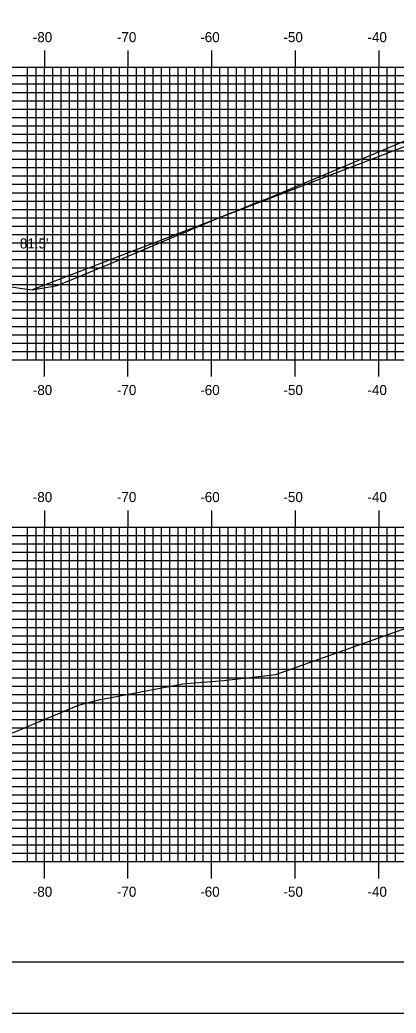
# Model space of a CAD drawing. Extents: x 852147 to 852490, y 364661 to 364881.
# Drawn here: x 852229.8 to 852274.8, y 364661.3 to 364780 of the extents above; entities that cross this region are included whole.
import ezdxf

# ---------------------------------------------------------------- set-up
doc = ezdxf.new("R2010")
doc.units = 0
for name, color, linetype in [('BORDER', 7, 'Continuous'), ('D_Roadway_SlopeLines', 7, 'Continuous'), ('D_Text_Standard', 7, 'Continuous'), ('H_V ANNOTATION', 7, 'Continuous'), ('MAJOR', 7, 'Continuous'), ('MINOR', 7, 'Continuous'), ('PLOT BOUNDARY', 7, 'Continuous'), ('S_Roadway_Centerline', 7, 'Continuous')]:
    doc.layers.add(name, color=color, linetype=linetype)

msp = doc.modelspace()

# ---------------------------------------------------------------- linework, layer by layer
at = {"layer": 'BORDER'}
msp.add_lwpolyline([(852163.16, 364667.37), (852483.16, 364667.37), (852483.16, 364877.37), (852163.16, 364877.37)], close=True, dxfattribs=at)
at = {"layer": 'D_Roadway_SlopeLines'}
msp.add_line((852285.76, 364768.68), (852231.3, 364747.76), dxfattribs=at)
at = {"layer": 'MAJOR'}
for p, q in [((852232.76, 364776.37), (852232.76, 364774.37)), ((852242.76, 364776.37), (852242.76, 364774.37)), ((852252.76, 364776.37), (852252.76, 364774.37)), ((852262.76, 364776.37), (852262.76, 364774.37)), ((852272.76, 364776.37), (852272.76, 364774.37)), ((852172.76, 364774.37), (852452.76, 364774.37)), ((852172.76, 364774.37), (852452.76, 364774.37)), ((852232.76, 364739.37), (852232.76, 364774.37)), ((852242.76, 364739.37), (852242.76, 364774.37)), ((852252.76, 364739.37), (852252.76, 364774.37)), ((852262.76, 364739.37), (852262.76, 364774.37)), ((852272.76, 364739.37), (852272.76, 364774.37)), ((852172.76, 364769.37), (852452.76, 364769.37)), ((852172.76, 364764.37), (852452.76, 364764.37)), ((852172.76, 364759.37), (852452.76, 364759.37)), ((852172.76, 364754.37), (852452.76, 364754.37)), ((852172.76, 364749.37), (852452.76, 364749.37)), ((852172.76, 364744.37), (852452.76, 364744.37)), ((852172.76, 364739.37), (852452.76, 364739.37)), ((852172.76, 364739.37), (852452.76, 364739.37)), ((852232.76, 364737.37), (852232.76, 364739.37)), ((852242.76, 364737.37), (852242.76, 364739.37)), ((852252.76, 364737.37), (852252.76, 364739.37)), ((852262.76, 364737.37), (852262.76, 364739.37)), ((852272.76, 364737.37), (852272.76, 364739.37)), ((852232.76, 364721.37), (852232.76, 364719.37)), ((852242.76, 364721.37), (852242.76, 364719.37)), ((852252.76, 364721.37), (852252.76, 364719.37)), ((852262.76, 364721.37), (852262.76, 364719.37)), ((852272.76, 364721.37), (852272.76, 364719.37)), ((852172.76, 364719.37), (852452.76, 364719.37)), ((852172.76, 364719.37), (852452.76, 364719.37)), ((852232.76, 364679.37), (852232.76, 364719.37)), ((852242.76, 364679.37), (852242.76, 364719.37)), ((852252.76, 364679.37), (852252.76, 364719.37)), ((852262.76, 364679.37), (852262.76, 364719.37)), ((852272.76, 364679.37), (852272.76, 364719.37)), ((852172.76, 364714.37), (852452.76, 364714.37)), ((852172.76, 364709.37), (852452.76, 364709.37)), ((852172.76, 364704.37), (852452.76, 364704.37)), ((852172.76, 364699.37), (852452.76, 364699.37)), ((852172.76, 364694.37), (852452.76, 364694.37)), ((852172.76, 364689.37), (852452.76, 364689.37)), ((852172.76, 364684.37), (852452.76, 364684.37)), ((852172.76, 364679.37), (852452.76, 364679.37)), ((852172.76, 364679.37), (852452.76, 364679.37)), ((852232.76, 364677.37), (852232.76, 364679.37)), ((852242.76, 364677.37), (852242.76, 364679.37)), ((852252.76, 364677.37), (852252.76, 364679.37)), ((852262.76, 364677.37), (852262.76, 364679.37)), ((852272.76, 364677.37), (852272.76, 364679.37))]:
    msp.add_line(p, q, dxfattribs=at)
at = {"layer": 'MINOR'}
for p, q in [((852230.76, 364739.37), (852230.76, 364774.37)), ((852231.76, 364739.37), (852231.76, 364774.37)), ((852233.76, 364739.37), (852233.76, 364774.37)), ((852234.76, 364739.37), (852234.76, 364774.37)), ((852235.76, 364739.37), (852235.76, 364774.37)), ((852236.76, 364739.37), (852236.76, 364774.37)), ((852237.76, 364739.37), (852237.76, 364774.37)), ((852238.76, 364739.37), (852238.76, 364774.37)), ((852239.76, 364739.37), (852239.76, 364774.37)), ((852240.76, 364739.37), (852240.76, 364774.37)), ((852241.76, 364739.37), (852241.76, 364774.37)), ((852243.76, 364739.37), (852243.76, 364774.37)), ((852244.76, 364739.37), (852244.76, 364774.37)), ((852245.76, 364739.37), (852245.76, 364774.37)), ((852246.76, 364739.37), (852246.76, 364774.37)), ((852247.76, 364739.37), (852247.76, 364774.37)), ((852248.76, 364739.37), (852248.76, 364774.37)), ((852249.76, 364739.37), (852249.76, 364774.37)), ((852250.76, 364739.37), (852250.76, 364774.37)), ((852251.76, 364739.37), (852251.76, 364774.37)), ((852253.76, 364739.37), (852253.76, 364774.37)), ((852254.76, 364739.37), (852254.76, 364774.37)), ((852255.76, 364739.37), (852255.76, 364774.37)), ((852256.76, 364739.37), (852256.76, 364774.37)), ((852257.76, 364739.37), (852257.76, 364774.37)), ((852258.76, 364739.37), (852258.76, 364774.37)), ((852259.76, 364739.37), (852259.76, 364774.37)), ((852260.76, 364739.37), (852260.76, 364774.37)), ((852261.76, 364739.37), (852261.76, 364774.37)), ((852263.76, 364739.37), (852263.76, 364774.37)), ((852264.76, 364739.37), (852264.76, 364774.37)), ((852265.76, 364739.37), (852265.76, 364774.37)), ((852266.76, 364739.37), (852266.76, 364774.37)), ((852267.76, 364739.37), (852267.76, 364774.37)), ((852268.76, 364739.37), (852268.76, 364774.37)), ((852269.76, 364739.37), (852269.76, 364774.37)), ((852270.76, 364739.37), (852270.76, 364774.37)), ((852271.76, 364739.37), (852271.76, 364774.37)), ((852273.76, 364739.37), (852273.76, 364774.37)), ((852274.76, 364739.37), (852274.76, 364774.37)), ((852172.76, 364773.37), (852452.76, 364773.37)), ((852172.76, 364772.37), (852452.76, 364772.37)), ((852172.76, 364771.37), (852452.76, 364771.37)), ((852172.76, 364770.37), (852452.76, 364770.37)), ((852172.76, 364768.37), (852452.76, 364768.37)), ((852172.76, 364767.37), (852452.76, 364767.37)), ((852172.76, 364766.37), (852452.76, 364766.37)), ((852172.76, 364765.37), (852452.76, 364765.37)), ((852172.76, 364763.37), (852452.76, 364763.37)), ((852172.76, 364762.37), (852452.76, 364762.37)), ((852172.76, 364761.37), (852452.76, 364761.37)), ((852172.76, 364760.37), (852452.76, 364760.37)), ((852172.76, 364758.37), (852452.76, 364758.37)), ((852172.76, 364757.37), (852452.76, 364757.37)), ((852172.76, 364756.37), (852452.76, 364756.37)), ((852172.76, 364755.37), (852452.76, 364755.37)), ((852172.76, 364753.37), (852452.76, 364753.37)), ((852172.76, 364752.37), (852452.76, 364752.37)), ((852172.76, 364751.37), (852452.76, 364751.37)), ((852172.76, 364750.37), (852452.76, 364750.37)), ((852172.76, 364748.37), (852452.76, 364748.37)), ((852172.76, 364747.37), (852452.76, 364747.37)), ((852172.76, 364746.37), (852452.76, 364746.37)), ((852172.76, 364745.37), (852452.76, 364745.37)), ((852172.76, 364743.37), (852452.76, 364743.37)), ((852172.76, 364742.37), (852452.76, 364742.37)), ((852172.76, 364741.37), (852452.76, 364741.37)), ((852172.76, 364740.37), (852452.76, 364740.37)), ((852172.76, 364718.37), (852452.76, 364718.37)), ((852230.76, 364679.37), (852230.76, 364719.37)), ((852231.76, 364679.37), (852231.76, 364719.37)), ((852233.76, 364679.37), (852233.76, 364719.37)), ((852234.76, 364679.37), (852234.76, 364719.37)), ((852235.76, 364679.37), (852235.76, 364719.37)), ((852236.76, 364679.37), (852236.76, 364719.37)), ((852237.76, 364679.37), (852237.76, 364719.37)), ((852238.76, 364679.37), (852238.76, 364719.37)), ((852239.76, 364679.37), (852239.76, 364719.37)), ((852240.76, 364679.37), (852240.76, 364719.37)), ((852241.76, 364679.37), (852241.76, 364719.37)), ((852243.76, 364679.37), (852243.76, 364719.37)), ((852244.76, 364679.37), (852244.76, 364719.37)), ((852245.76, 364679.37), (852245.76, 364719.37)), ((852246.76, 364679.37), (852246.76, 364719.37)), ((852247.76, 364679.37), (852247.76, 364719.37)), ((852248.76, 364679.37), (852248.76, 364719.37)), ((852249.76, 364679.37), (852249.76, 364719.37)), ((852250.76, 364679.37), (852250.76, 364719.37)), ((852251.76, 364679.37), (852251.76, 364719.37)), ((852253.76, 364679.37), (852253.76, 364719.37)), ((852254.76, 364679.37), (852254.76, 364719.37)), ((852255.76, 364679.37), (852255.76, 364719.37)), ((852256.76, 364679.37), (852256.76, 364719.37)), ((852257.76, 364679.37), (852257.76, 364719.37)), ((852258.76, 364679.37), (852258.76, 364719.37)), ((852259.76, 364679.37), (852259.76, 364719.37)), ((852260.76, 364679.37), (852260.76, 364719.37)), ((852261.76, 364679.37), (852261.76, 364719.37)), ((852263.76, 364679.37), (852263.76, 364719.37)), ((852264.76, 364679.37), (852264.76, 364719.37)), ((852265.76, 364679.37), (852265.76, 364719.37)), ((852266.76, 364679.37), (852266.76, 364719.37)), ((852267.76, 364679.37), (852267.76, 364719.37)), ((852268.76, 364679.37), (852268.76, 364719.37)), ((852269.76, 364679.37), (852269.76, 364719.37)), ((852270.76, 364679.37), (852270.76, 364719.37)), ((852271.76, 364679.37), (852271.76, 364719.37)), ((852273.76, 364679.37), (852273.76, 364719.37)), ((852274.76, 364679.37), (852274.76, 364719.37)), ((852172.76, 364717.37), (852452.76, 364717.37)), ((852172.76, 364716.37), (852452.76, 364716.37)), ((852172.76, 364715.37), (852452.76, 364715.37)), ((852172.76, 364713.37), (852452.76, 364713.37)), ((852172.76, 364712.37), (852452.76, 364712.37)), ((852172.76, 364711.37), (852452.76, 364711.37)), ((852172.76, 364710.37), (852452.76, 364710.37)), ((852172.76, 364708.37), (852452.76, 364708.37)), ((852172.76, 364707.37), (852452.76, 364707.37)), ((852172.76, 364706.37), (852452.76, 364706.37)), ((852172.76, 364705.37), (852452.76, 364705.37)), ((852172.76, 364703.37), (852452.76, 364703.37)), ((852172.76, 364702.37), (852452.76, 364702.37)), ((852172.76, 364701.37), (852452.76, 364701.37)), ((852172.76, 364700.37), (852452.76, 364700.37)), ((852172.76, 364698.37), (852452.76, 364698.37)), ((852172.76, 364697.37), (852452.76, 364697.37)), ((852172.76, 364696.37), (852452.76, 364696.37)), ((852172.76, 364695.37), (852452.76, 364695.37)), ((852172.76, 364693.37), (852452.76, 364693.37)), ((852172.76, 364692.37), (852452.76, 364692.37)), ((852172.76, 364691.37), (852452.76, 364691.37)), ((852172.76, 364690.37), (852452.76, 364690.37)), ((852172.76, 364688.37), (852452.76, 364688.37)), ((852172.76, 364687.37), (852452.76, 364687.37)), ((852172.76, 364686.37), (852452.76, 364686.37)), ((852172.76, 364685.37), (852452.76, 364685.37)), ((852172.76, 364683.37), (852452.76, 364683.37)), ((852172.76, 364682.37), (852452.76, 364682.37)), ((852172.76, 364681.37), (852452.76, 364681.37)), ((852172.76, 364680.37), (852452.76, 364680.37))]:
    msp.add_line(p, q, dxfattribs=at)
at = {"layer": 'PLOT BOUNDARY'}
msp.add_lwpolyline([(852146.97, 364661.25), (852486.97, 364661.25), (852486.97, 364881.25), (852146.97, 364881.25)], close=True, dxfattribs=at)
at = {"layer": 'S_Roadway_Centerline'}
for points in [[(852224.08, 364748.8), (852230.42, 364747.89), (852231.3, 364747.76), (852233.36, 364748.09), (852234.28, 364748.26), (852235.28, 364748.65), (852241.08, 364751.04), (852254.88, 364756.88), (852255.35, 364757.03), (852256.42, 364757.46), (852257.84, 364758.08), (852259.46, 364758.66), (852280.54, 364767.54)], [(852228.88, 364694.73), (852235.14, 364697.36), (852236.84, 364698.07), (852239.27, 364698.72), (852249.31, 364700.62), (852254.2, 364701.02), (852260.43, 364701.74), (852280.28, 364708.79), (852284.03, 364710.04), (852284.87, 364710.01), (852295.09, 364709.66), (852297.1, 364709.56), (852299.39, 364709.49), (852305.93, 364709.05), (852313.49, 364708.62), (852316.43, 364708.48), (852318.4, 364708.34), (852330.85, 364706.15), (852335.84, 364705.07), (852344.14, 364703.12), (852356.99, 364700.16), (852360.48, 364700.01), (852373.76, 364699.54)]]:
    msp.add_lwpolyline(points, dxfattribs=at)

# ---------------------------------------------------------------- texts
at = {"layer": 'D_Text_Standard'}
msp.add_text("81.5'", height=1.2, dxfattribs=at).set_placement((852229.83, 364752.7))
at = {"layer": 'H_V ANNOTATION'}
for s, p in [('-80', (852231.38, 364777.37)), ('-70', (852241.44, 364777.37)), ('-60', (852251.41, 364777.37)), ('-50', (852261.36, 364777.37)), ('-40', (852271.41, 364777.37)), ('-80', (852231.38, 364735.17)), ('-70', (852241.44, 364735.17)), ('-60', (852251.41, 364735.17)), ('-50', (852261.36, 364735.17)), ('-40', (852271.41, 364735.17)), ('-80', (852231.38, 364722.37)), ('-70', (852241.44, 364722.37)), ('-60', (852251.41, 364722.37)), ('-50', (852261.36, 364722.37)), ('-40', (852271.41, 364722.37)), ('-80', (852231.38, 364675.17)), ('-70', (852241.44, 364675.17)), ('-60', (852251.41, 364675.17)), ('-50', (852261.36, 364675.17)), ('-40', (852271.41, 364675.17))]:
    msp.add_text(s, height=1.2, dxfattribs=at).set_placement(p)

doc.saveas('drawing.dxf')
